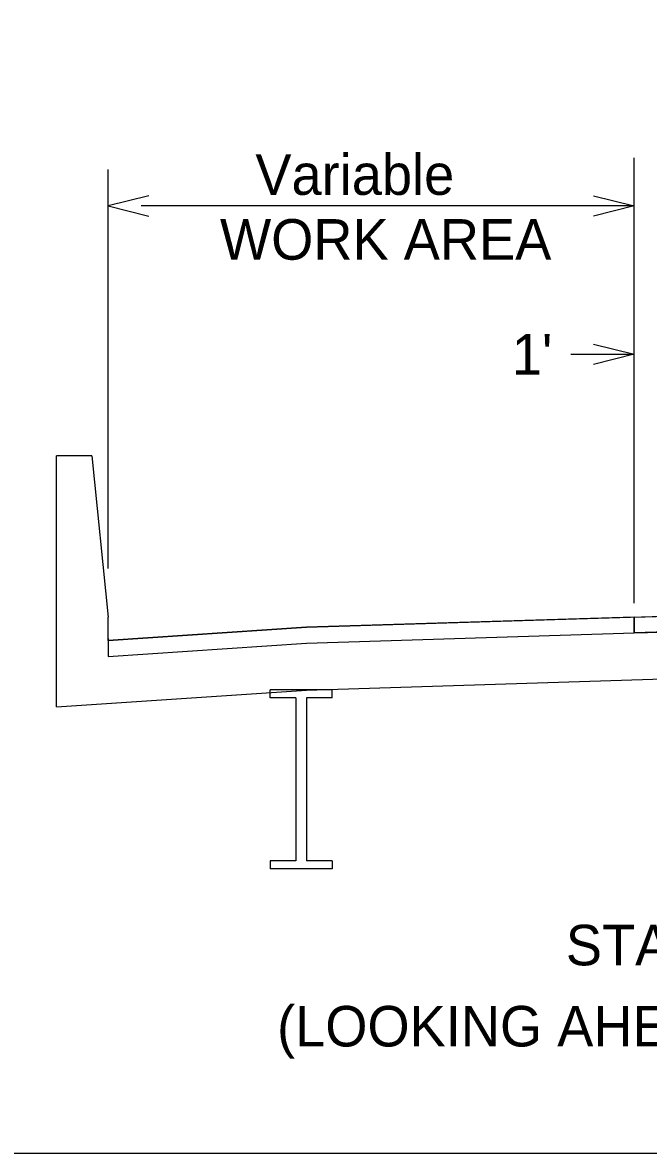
# Model space of a CAD drawing. Extents: x 10133 to 81668, y 7924 to 11018.
# Drawn here: x 11023 to 11596, y 7924 to 8960 of the extents above; entities that cross this region are included whole.
import ezdxf

# ---------------------------------------------------------------- set-up
doc = ezdxf.new("R2010")
doc.units = 0
for name, color, linetype in [('dsnCellElements', 7, 'Continuous'), ('SheetAddendum', 7, 'Continuous'), ('SheetBorder', 7, 'Continuous'), ('ShtPlotIdentification', 7, 'Continuous')]:
    doc.layers.add(name, color=color, linetype=linetype)

msp = doc.modelspace()

# ---------------------------------------------------------------- linework, layer by layer
at = {"layer": 'dsnCellElements'}
for p, q in [((11053.7, 8332.9), (11053.7, 8562.9)), ((11086.2, 8562.9), (11053.7, 8562.9)), ((11086.2, 8562.9), (11101.2, 8415.1)), ((11101.2, 8393.6), (11101.2, 8415.1)), ((11283, 8405.8), (11643, 8417)), ((11583, 8415.1), (11583, 8400.6)), ((11101.2, 8393.6), (11283, 8405.8)), ((11283, 8391.2), (11583, 8400.6)), ((11583, 8400.6), (11644, 8402.5)), ((11101.2, 8395.6), (11101.2, 8379)), ((11101.2, 8379), (11283, 8391.2)), ((11283, 8348.3), (11643, 8359.5)), ((11053.7, 8332.9), (11283, 8348.3)), ((11249.5, 8341.3), (11249.5, 8348.5)), ((11306.5, 8348.5), (11249.5, 8348.5)), ((11306.5, 8341.3), (11306.5, 8348.5)), ((11273, 8341.3), (11249.5, 8341.3)), ((11273, 8341.3), (11273, 8191.9)), ((11306.5, 8341.3), (11283, 8341.3)), ((11283, 8341.3), (11283, 8191.9)), ((11273, 8191.9), (11249.5, 8191.9)), ((11249.5, 8191.9), (11249.5, 8184.7)), ((11306.5, 8191.9), (11283, 8191.9)), ((11306.5, 8191.9), (11306.5, 8184.7)), ((11306.5, 8184.7), (11249.5, 8184.7))]:
    msp.add_line(p, q, dxfattribs=at)
at = {"layer": 'SheetAddendum'}
for p, q in [((11583, 8427.9), (11583, 8835.8)), ((11101.2, 8459.5), (11101.2, 8825)), ((11583, 8791.7), (11131.2, 8791.7)), ((11525.2, 8655.8), (11583, 8655.8))]:
    msp.add_line(p, q, dxfattribs=at)
for points in [[(11138.3, 8800.9), (11101.2, 8791.7), (11138.3, 8782.4)], [(11545.9, 8800.9), (11583, 8791.7), (11545.9, 8782.4)], [(11545.9, 8665.1), (11583, 8655.8), (11545.9, 8646.5)]]:
    msp.add_lwpolyline(points, dxfattribs=at)
at = {"layer": 'SheetBorder'}
msp.add_lwpolyline([(10132.5, 9944), (13267.5, 9944), (13267.5, 7924), (10132.5, 7924)], close=True, dxfattribs=at)
at = {"layer": 'ShtPlotIdentification'}
for points in [[(11101.2, 8379), (11283, 8391.2), (11583, 8400.6), (11583, 8415.1), (11283, 8405.8), (11101.2, 8393.6)], [(12094, 8388.7), (12004, 8391.3), (11644, 8402.5), (11583, 8400.6), (11583, 8415.1), (11644, 8417), (12004, 8405.8), (12094, 8403.3)]]:
    msp.add_lwpolyline(points, close=True, dxfattribs=at)

# ---------------------------------------------------------------- texts
at = {"layer": 'SheetAddendum'}
for s, p in [('Variable', (11236, 8801.8)), ('WORK AREA', (11203.6, 8742.4)), ("1'", (11471, 8637.2)), ('STAGE 2', (11520.5, 8096.2)), ('(LOOKING AHEAD STATION)', (11255.9, 8021.9))]:
    msp.add_text(s, height=37.15, dxfattribs=at).set_placement(p)

doc.saveas('drawing.dxf')
